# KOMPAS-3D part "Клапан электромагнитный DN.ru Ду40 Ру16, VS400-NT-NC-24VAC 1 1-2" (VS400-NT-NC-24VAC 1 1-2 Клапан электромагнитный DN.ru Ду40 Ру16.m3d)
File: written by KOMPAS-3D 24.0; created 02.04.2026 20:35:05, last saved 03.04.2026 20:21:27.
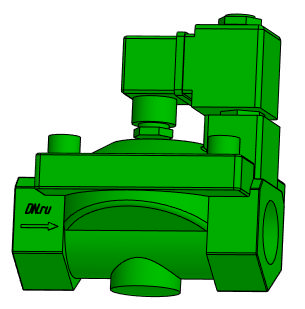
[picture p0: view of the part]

Document properties: Автор: artio; Полное имя файла: C:\Users\artio\OneDrive\Рабочий стол\Клапан электромагнитный DN.ru\VS400-NT-NC\VS400-NT-NC-24VAC 1 1-2 Клапан электромагнитный DN.ru Ду40 Ру16.m3d

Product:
- Body: Тело 1  | qty 1
    Масса: 4.144257
- Part/product: Клапан электромагнитный DN.ru Ду40 Ру16  | designation VS400-NT-NC-24VAC 1 1-2
    Масса: 2.321
    Раздел спецификации: Прочие изделия
    Примечание: D130-05496
    additional columns: ef56311e-7521-43dc-8291-0e6108b3d81d; VS400-ET-NC-220VAC 1 1-2; artio; c; Шероховатость не задана; Да

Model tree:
1. Операция без истории:1

Expressions: VS400-NT-NC-24VAC 1 1-2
